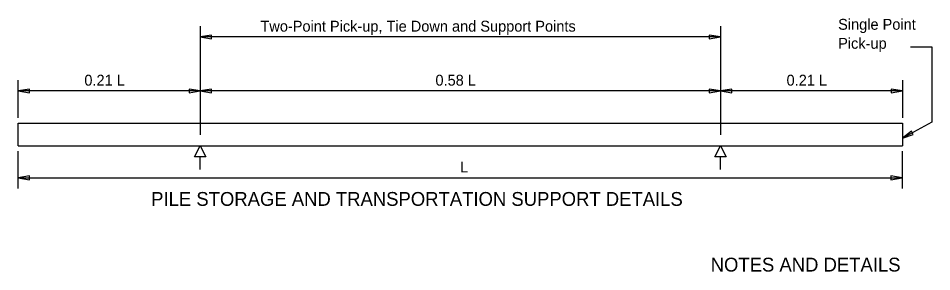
# Model space of a CAD drawing. Extents: x 0.4 to 30.4, y 0.1 to 19.4.
# Drawn here: x 17.73 to 30.43, y 0.12 to 3.64 of the extents above; entities that cross this region are included whole.
import ezdxf

# ---------------------------------------------------------------- set-up
doc = ezdxf.new("R2010")
doc.units = 0
for name, color, linetype in [('Dimension', 7, 'Continuous'), ('SheetPileConc', 7, 'Continuous'), ('TextStructures', 7, 'Continuous')]:
    doc.layers.add(name, color=color, linetype=linetype)

msp = doc.modelspace()

# ---------------------------------------------------------------- linework, layer by layer
at = {"layer": 'Dimension'}
for p, q in [((20.259, 3.529), (20.259, 2.02)), ((27.492, 3.529), (27.492, 2.02)), ((27.492, 3.381), (20.259, 3.381)), ((17.729, 2.26), (17.729, 2.779)), ((30.022, 2.779), (30.022, 2.26)), ((20.259, 2.631), (17.729, 2.631)), ((27.492, 2.631), (20.259, 2.631)), ((30.022, 2.631), (27.492, 2.631)), ((17.729, 1.277), (17.729, 1.797)), ((30.022, 1.277), (30.022, 1.797)), ((20.26, 1.541), (20.26, 1.715)), ((27.493, 1.541), (27.493, 1.715)), ((17.729, 1.426), (30.022, 1.426))]:
    msp.add_line(p, q, dxfattribs=at)
for points in [[(20.259, 3.381), (20.415, 3.355), (20.415, 3.407)], [(27.492, 3.381), (27.336, 3.407), (27.336, 3.355)], [(17.729, 2.631), (17.886, 2.605), (17.886, 2.657)], [(20.259, 2.631), (20.103, 2.657), (20.103, 2.605)], [(20.259, 2.631), (20.415, 2.605), (20.415, 2.657)], [(27.492, 2.631), (27.336, 2.657), (27.336, 2.605)], [(27.492, 2.631), (27.648, 2.605), (27.648, 2.657)], [(30.022, 2.631), (29.865, 2.657), (29.865, 2.605)], [(30.023, 1.977), (30.172, 2.028), (30.147, 2.075)], [(20.259, 1.871), (20.338, 1.715), (20.18, 1.715)], [(27.492, 1.871), (27.571, 1.715), (27.413, 1.715)], [(17.729, 1.426), (17.886, 1.399), (17.886, 1.452)], [(30.015, 1.426), (29.859, 1.452), (29.859, 1.399)]]:
    msp.add_lwpolyline(points, close=True, dxfattribs=at)
msp.add_lwpolyline([(30.131, 3.246), (30.428, 3.246), (30.428, 2.199), (30.023, 1.977)], dxfattribs=at)
at = {"layer": 'SheetPileConc'}
for p, q in [((17.729, 2.186), (30.022, 2.186)), ((17.729, 1.871), (17.729, 2.186)), ((30.022, 2.186), (30.022, 1.871)), ((17.729, 1.871), (30.022, 1.871))]:
    msp.add_line(p, q, dxfattribs=at)

# ---------------------------------------------------------------- texts
at = {"layer": 'Dimension'}
for s, p in [('Single Point', (29.127, 3.481)), ('Pick-up', (29.127, 3.217))]:
    msp.add_text(s, height=0.1512, dxfattribs=at).set_placement(p)
at = {"layer": 'TextStructures'}
for s, height, p in [('Two-Point Pick-up, Tie Down and Support Points', 0.1512, (21.096, 3.455)), ('0.21 L', 0.1512, (18.648, 2.705)), ('0.58 L', 0.1512, (23.529, 2.705)), ('0.21 L', 0.1512, (28.41, 2.705)), ('L', 0.151, (23.872, 1.5)), ('PILE STORAGE AND TRANSPORTATION SUPPORT DETAILS', 0.192, (19.577, 1.036)), ('NOTES AND DETAILS', 0.192, (27.355, 0.124))]:
    msp.add_text(s, height=height, dxfattribs=at).set_placement(p)

doc.saveas('drawing.dxf')
